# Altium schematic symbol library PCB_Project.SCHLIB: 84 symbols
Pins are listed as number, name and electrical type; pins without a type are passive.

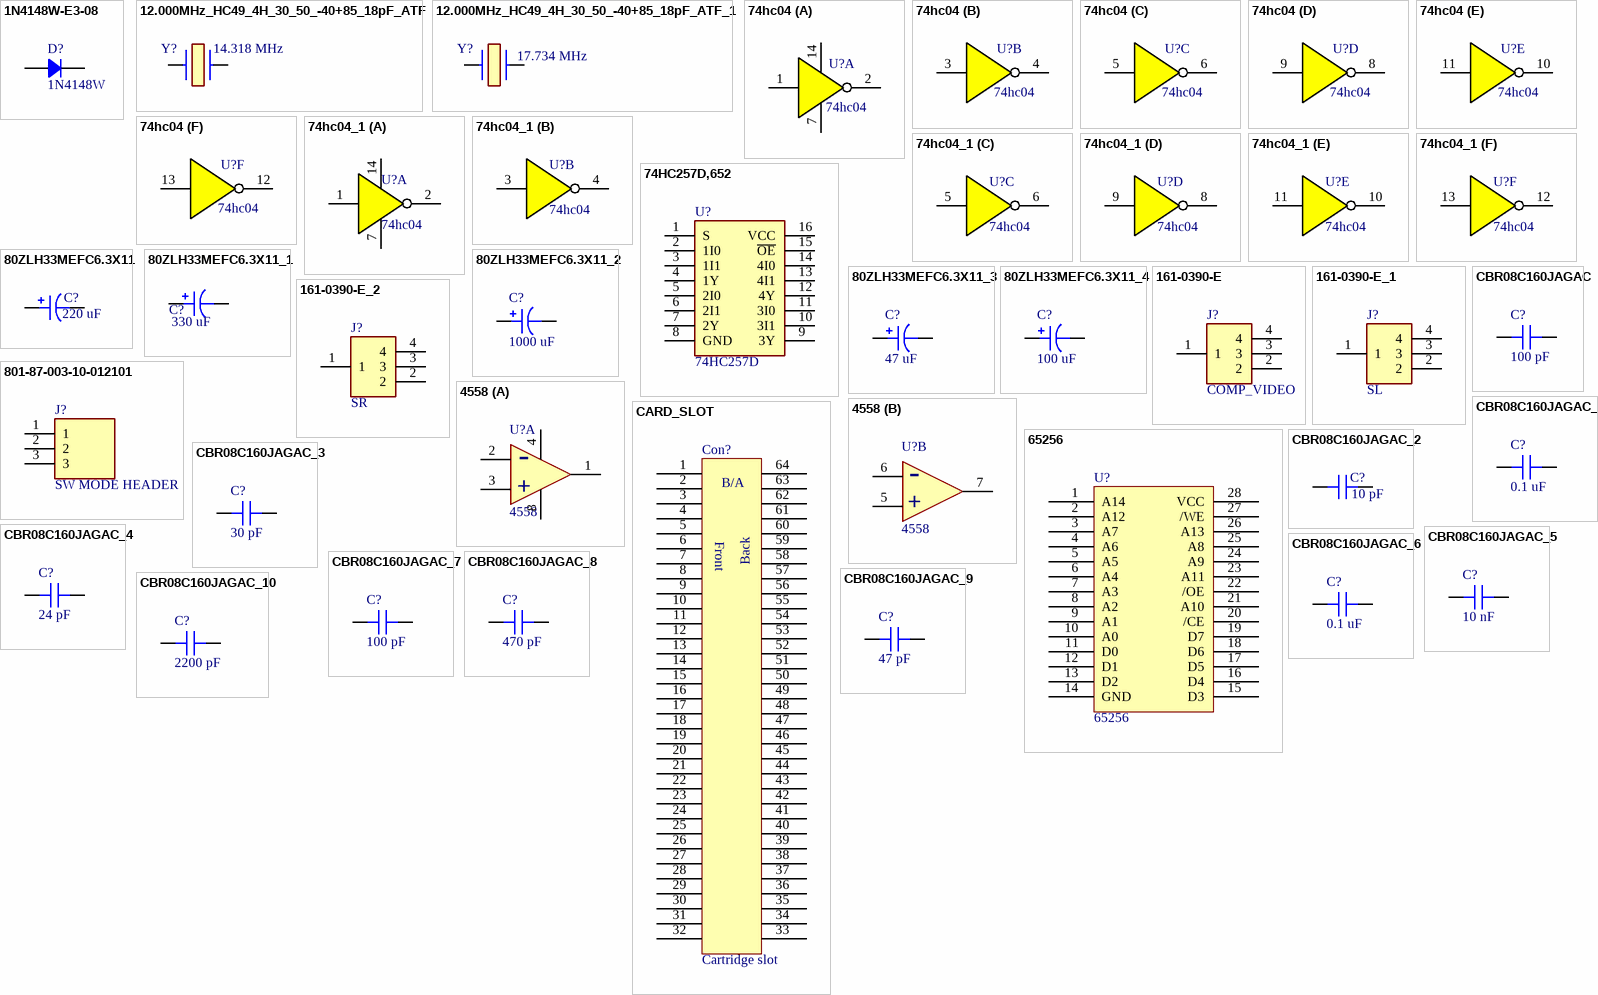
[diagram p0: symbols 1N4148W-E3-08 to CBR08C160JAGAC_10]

## 1N4148W-E3-08
designator D?, comment 1N4148W
DIODE GEN PURP 75V 150MA SOD123; Part Number: 1N4148W-E3-08; Manufacturer: Vishay Semiconductor Diodes Division; Current - Reverse Leakage @ Vr: 100µA @ 100V; Diode Type: Standard; Reverse Recovery Time (trr): 4ns; Speed: Small Signal =< 200mA (Io), Any Speed; Voltage - Forward (Vf) (Max) @ If: 1.2V @ 100mA
footprint SOD-123
pins: 1, 2

## 12.000MHz_HC49_4H_30_50_-40+85_18pF_ATF
designator Y?, comment 14.318 MHz
Crystal or Oscillator; Manufacturer_Name: EUROQUARTZ; Manufacturer_Part_Number: 12.000MHz HC49/4H/30/50/-40+85/18pF/ATF
footprint 12000MHzHC494H3050408518pFATF
pins: 1 CRYSTAL_1, 2 CRYSTAL_2

## 12.000MHz_HC49_4H_30_50_-40+85_18pF_ATF_1
designator Y?, comment 17.734 MHz
Crystal or Oscillator; Manufacturer_Name: EUROQUARTZ; Manufacturer_Part_Number: 12.000MHz HC49/4H/30/50/-40+85/18pF/ATF
footprint 12000MHzHC494H3050408518pFATF
pins: 1 CRYSTAL_1, 2 CRYSTAL_2

## 74hc04
designator U?
footprint SOIC127P600X175-14N
part A pins: 1 45, 2 46, 7 gnd, 14 vcc
part B pins: 3 45, 4 46
part C pins: 5 45, 6 46
part D pins: 8 46, 9 45
part E pins: 10 46, 11 45
part F pins: 12 46, 13 45

## 74hc04_1
designator U?, comment 74hc04
footprint SOIC127P600X175-14N
part A pins: 1 45, 2 46, 7 gnd, 14 vcc
part B pins: 3 45, 4 46
part C pins: 5 45, 6 46
part D pins: 8 46, 9 45
part E pins: 10 46, 11 45
part F pins: 12 46, 13 45

## 74HC257D,652
designator U?, comment 74HC257D
Integrated Circuit; Manufacturer_Name: Nexperia; Manufacturer_Part_Number: 74HC257D,652
footprint 74HC257D652
pins: 1 S, 2 1I0, 3 1I1, 4 1Y, 5 2I0, 6 2I1, 7 2Y, 8 GND, 9 3Y, 10 3I1, 11 3I0, 12 4Y, 13 4I1, 14 4I0, 15 ~{OE}, 16 VCC

## 80ZLH33MEFC6.3X11
designator C?, comment 220 uF
CAP ALUM 33UF 20% 80V RADIAL; Part Number: 80ZLH33MEFC6.3X11; manufacturer: Rubycon; Capacitance: 33µF; Lifetime @ Temp.: 6000 Hrs @ 105°C; Polarization: Polar; value: 33µF; Impedance: 570 mOhms; Ripple Current @ Low Frequency: 112.14mA @ 120Hz
footprint CAP TH ALUM ELEC D6.30mm S2.50mm H12.50mm
pins: 1, 2

## 80ZLH33MEFC6.3X11_1
designator C?, comment 330 uF
CAP ALUM 33UF 20% 80V RADIAL; Part Number: 80ZLH33MEFC6.3X11; manufacturer: Rubycon; Capacitance: 33µF; Lifetime @ Temp.: 6000 Hrs @ 105°C; Polarization: Polar; value: 33µF; Impedance: 570 mOhms; Ripple Current @ Low Frequency: 112.14mA @ 120Hz
footprint CAP TH ALUM ELEC D6.30mm S2.50mm H12.50mm
pins: 1, 2

## 80ZLH33MEFC6.3X11_2
designator C?, comment 1000 uF
CAP ALUM 33UF 20% 80V RADIAL; Part Number: 80ZLH33MEFC6.3X11; manufacturer: Rubycon; Capacitance: 33µF; Lifetime @ Temp.: 6000 Hrs @ 105°C; Polarization: Polar; value: 33µF; Impedance: 570 mOhms; Ripple Current @ Low Frequency: 112.14mA @ 120Hz
footprint CAP TH ALUM ELEC D6.30mm S2.50mm H12.50mm
pins: 1, 2

## 80ZLH33MEFC6.3X11_3
designator C?, comment 47 uF
CAP ALUM 33UF 20% 80V RADIAL; Part Number: 80ZLH33MEFC6.3X11; manufacturer: Rubycon; Capacitance: 33µF; Lifetime @ Temp.: 6000 Hrs @ 105°C; Polarization: Polar; value: 33µF; Impedance: 570 mOhms; Ripple Current @ Low Frequency: 112.14mA @ 120Hz
footprint CAP TH ALUM ELEC D6.30mm S2.50mm H12.50mm
pins: 1, 2

## 80ZLH33MEFC6.3X11_4
designator C?, comment 100 uF
CAP ALUM 33UF 20% 80V RADIAL; Part Number: 80ZLH33MEFC6.3X11; manufacturer: Rubycon; Capacitance: 33µF; Lifetime @ Temp.: 6000 Hrs @ 105°C; Polarization: Polar; value: 33µF; Impedance: 570 mOhms; Ripple Current @ Low Frequency: 112.14mA @ 120Hz
footprint CAP TH ALUM ELEC D6.30mm S2.50mm H12.50mm
pins: 1, 2

## 161-0390-E
designator J?, comment COMP_VIDEO
Connector; Manufacturer_Name: Kobiconn; Manufacturer_Part_Number: 161-0390-E
footprint 1610390E
pins: 1, 2, 3, 4

## 161-0390-E_1
designator J?, comment SL
Connector; Manufacturer_Name: Kobiconn; Manufacturer_Part_Number: 161-0390-E
footprint 1610390E
pins: 1, 2, 3, 4

## 161-0390-E_2
designator J?, comment SR
Connector; Manufacturer_Name: Kobiconn; Manufacturer_Part_Number: 161-0390-E
footprint 1610390E
pins: 1, 2, 3, 4

## 801-87-003-10-012101
designator J?, comment SW MODE HEADER
Connector; Manufacturer_Name: Preci-Dip; Manufacturer_Part_Number: 801-87-003-10-012101
footprint 8018700310012101
pins: 1, 2, 3

## 4558
designator U?
Operation amp; Manufacturer_Name: Texas Instruments; Manufacturer_Part_Number: OPA2134UA
footprint SOIC127P600X175-8N
part A pins: 1 13, 2 -, 3 10, 4 11, 8 12
part B pins: 5 11, 6 -, 7 14

## 65256
designator U?
footprint SOP28
pins: 1 A14, 2 A12, 3 A7, 4 A6, 5 A5, 6 A4, 7 A3, 8 A2, 9 A1, 10 A0, 11 D0, 12 D1, 13 D2, 14 GND, 15 D3, 16 D4, 17 D5, 18 D6, 19 D7, 20 /CE, 21 A10, 22 /OE, 23 A11, 24 A9, 25 A8, 26 A13, 27 /WE, 28 VCC

## CARD_SLOT
designator Con?, comment Cartridge slot
footprint CARD_SLOT
pins: 1 Ain, 2 Ain, 3 Ain, 4 Ain, 5 Ain, 6 Ain, 7 Ain, 8 Ain, 9 Ain, 10 Ain, 11 Ain, 12 Ain, 13 Ain, 14 Ain, 15 Ain, 16 Ain, 17 Ain, 18 Ain, 19 Ain, 20 Ain, 21 Ain, 22 Ain, 23 Ain, 24 Ain, 25 Ain, 26 Ain, 27 Ain, 28 Ain, 29 Ain, 30 Ain, 31 Ain, 32 Ain, 33 50, 34 51, 35 52, 36 53, 37 54, 38 55, 39 56, 40 57, 41 58, 42 59, 43 60, 44 61, 45 62, 46 63, 47 64, 48 65, 49 66, 50 67, 51 68, 52 69, 53 70, 54 71, 55 72, 56 73, 57 74, 58 75, 59 76, 60 77, 61 78, 62 79, 63 80, 64 81

## CBR08C160JAGAC
designator C?, comment 100 pF
CAP CER 16PF 250V C0G/NP0 0805; Part Number: CBR08C160JAGAC; manufacturer: KEMET; Temperature Coefficient: C0G, NP0; Tolerance: ±5%
footprint CAP 0805_2012
pins: 1, 2

## CBR08C160JAGAC_1
designator C?, comment 0.1 uF
CAP CER 16PF 250V C0G/NP0 0805; Part Number: CBR08C160JAGAC; manufacturer: KEMET; Temperature Coefficient: C0G, NP0; Tolerance: ±5%
footprint CAP 0805_2012
pins: 1, 2

## CBR08C160JAGAC_2
designator C?, comment 10 pF
CAP CER 16PF 250V C0G/NP0 0805; Part Number: CBR08C160JAGAC; manufacturer: KEMET; Temperature Coefficient: C0G, NP0; Tolerance: ±5%
footprint CAP 0805_2012
pins: 1, 2

## CBR08C160JAGAC_3
designator C?, comment 30 pF
CAP CER 16PF 250V C0G/NP0 0805; Part Number: CBR08C160JAGAC; manufacturer: KEMET; Temperature Coefficient: C0G, NP0; Tolerance: ±5%
footprint CAP 0805_2012
pins: 1, 2

## CBR08C160JAGAC_4
designator C?, comment 24 pF
CAP CER 16PF 250V C0G/NP0 0805; Part Number: CBR08C160JAGAC; manufacturer: KEMET; Temperature Coefficient: C0G, NP0; Tolerance: ±5%
footprint CAP 0805_2012
pins: 1, 2

## CBR08C160JAGAC_5
designator C?, comment 10 nF
CAP CER 16PF 250V C0G/NP0 0805; Part Number: CBR08C160JAGAC; manufacturer: KEMET; Temperature Coefficient: C0G, NP0; Tolerance: ±5%
footprint CAP 0805_2012
pins: 1, 2

## CBR08C160JAGAC_6
designator C?, comment 0.1 uF
CAP CER 16PF 250V C0G/NP0 0805; Part Number: CBR08C160JAGAC; manufacturer: KEMET; Temperature Coefficient: C0G, NP0; Tolerance: ±5%
footprint CAP 0805_2012
pins: 1, 2

## CBR08C160JAGAC_7
designator C?, comment 100 pF
CAP CER 16PF 250V C0G/NP0 0805; Part Number: CBR08C160JAGAC; manufacturer: KEMET; Temperature Coefficient: C0G, NP0; Tolerance: ±5%
footprint CAP 0805_2012
pins: 1, 2

## CBR08C160JAGAC_8
designator C?, comment 470 pF
CAP CER 16PF 250V C0G/NP0 0805; Part Number: CBR08C160JAGAC; manufacturer: KEMET; Temperature Coefficient: C0G, NP0; Tolerance: ±5%
footprint CAP 0805_2012
pins: 1, 2

## CBR08C160JAGAC_9
designator C?, comment 47 pF
CAP CER 16PF 250V C0G/NP0 0805; Part Number: CBR08C160JAGAC; manufacturer: KEMET; Temperature Coefficient: C0G, NP0; Tolerance: ±5%
footprint CAP 0805_2012
pins: 1, 2

## CBR08C160JAGAC_10
designator C?, comment 2200 pF
CAP CER 16PF 250V C0G/NP0 0805; Part Number: CBR08C160JAGAC; manufacturer: KEMET; Temperature Coefficient: C0G, NP0; Tolerance: ±5%
footprint CAP 0805_2012
pins: 1, 2

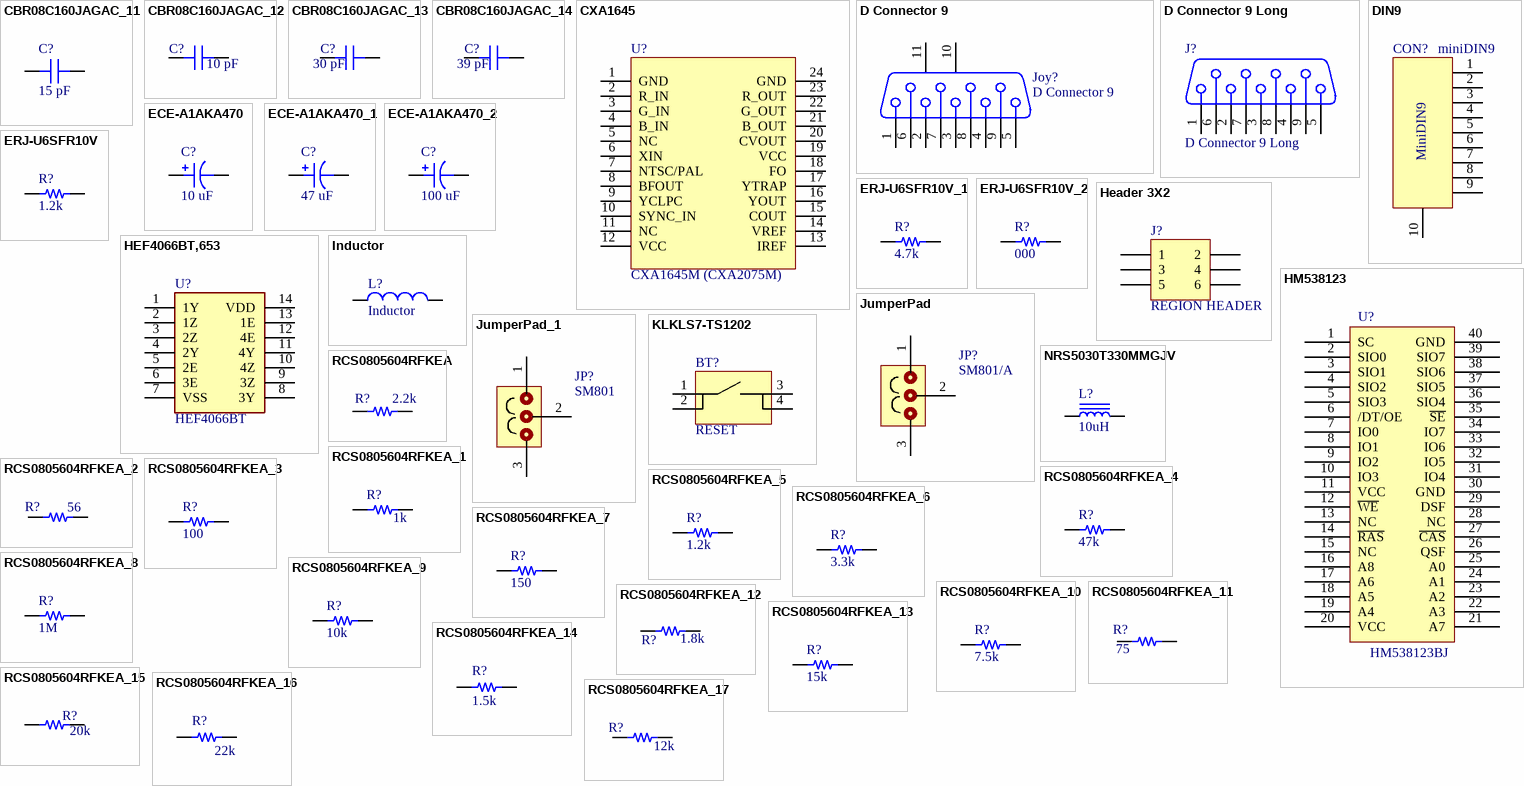
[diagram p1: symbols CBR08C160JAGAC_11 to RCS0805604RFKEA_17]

## CBR08C160JAGAC_11
designator C?, comment 15 pF
CAP CER 16PF 250V C0G/NP0 0805; Part Number: CBR08C160JAGAC; manufacturer: KEMET; Temperature Coefficient: C0G, NP0; Tolerance: ±5%
footprint CAP 0805_2012
pins: 1, 2

## CBR08C160JAGAC_12
designator C?, comment 10 pF
CAP CER 16PF 250V C0G/NP0 0805; Part Number: CBR08C160JAGAC; manufacturer: KEMET; Temperature Coefficient: C0G, NP0; Tolerance: ±5%
footprint CAP 0805_2012
pins: 1, 2

## CBR08C160JAGAC_13
designator C?, comment 30 pF
CAP CER 16PF 250V C0G/NP0 0805; Part Number: CBR08C160JAGAC; manufacturer: KEMET; Temperature Coefficient: C0G, NP0; Tolerance: ±5%
footprint CAP 0805_2012
pins: 1, 2

## CBR08C160JAGAC_14
designator C?, comment 39 pF
CAP CER 16PF 250V C0G/NP0 0805; Part Number: CBR08C160JAGAC; manufacturer: KEMET; Temperature Coefficient: C0G, NP0; Tolerance: ±5%
footprint CAP 0805_2012
pins: 1, 2

## CXA1645
designator U?, comment CXA1645M (CXA2075M)
Video coder
footprint SOP24N (SOP, 24-Leads, Body 15,90x5,65mm, Pitch 1,27mm, IPC Medium Density)
pins: 1 GND, 2 R_IN, 3 G_IN, 4 B_IN, 5 NC, 6 XIN, 7 NTSC/PAL, 8 BFOUT, 9 YCLPC, 10 SYNC_IN, 11 NC, 12 VCC, 13 IREF, 14 VREF, 15 COUT, 16 YOUT, 17 YTRAP, 18 FO, 19 VCC, 20 CVOUT, 21 B_OUT, 22 G_OUT, 23 R_OUT, 24 GND

## D Connector 9
designator Joy?
Receptacle Assembly, 9 Position, Right Angle; PackageDocument: O; Positions: 9
footprint DSUB1.385-2H9 (Connector; D Subminiature; 9 Position; Right Angle; Pitch 1.385 mm)
signal-integrity model Connector
pins: 1, 2, 3, 4, 5, 6, 7, 8, 9, 10 MH1, 11 MH2

## D Connector 9 Long
designator J?
Receptacle Assembly, 9 Position, Right Angle; PackageDocument: O; Positions: 9
footprint DSUB1.385-2H9_LONG (Connector; D Subminiature; 9 Position; Right Angle; Pitch 1.385 mm)
pins: 1, 2, 3, 4, 5, 6, 7, 8, 9

## DIN9
designator CON?, comment miniDIN9
footprint miniDIN9
pins: 1 7, 2 8, 3 9, 4 10, 5 11, 6 12, 7 13, 8 14, 9 15, 10 16

## ECE-A1AKA470
designator C?, comment 10 uF
CAP ALUM 47UF 20% 10V RADIAL; Part Number: ECE-A1AKA470; manufacturer: Panasonic Electronic Components; Capacitance: 47µF; Lifetime @ Temp.: 1000 Hrs @ 85°C; Polarization: Polar; Ripple Current @ High Frequency: 110.5mA @ 10kHz; value: 47µF
footprint CAP TH ALUM ELEC D5.00mm S2.00mm H7.00mm
pins: 1, 2

## ECE-A1AKA470_1
designator C?, comment 47 uF
CAP ALUM 47UF 20% 10V RADIAL; Part Number: ECE-A1AKA470; manufacturer: Panasonic Electronic Components; Capacitance: 47µF; Lifetime @ Temp.: 1000 Hrs @ 85°C; Polarization: Polar; Ripple Current @ High Frequency: 110.5mA @ 10kHz; value: 47µF
footprint CAP TH ALUM ELEC D5.00mm S2.00mm H7.00mm
pins: 1, 2

## ECE-A1AKA470_2
designator C?, comment 100 uF
CAP ALUM 47UF 20% 10V RADIAL; Part Number: ECE-A1AKA470; manufacturer: Panasonic Electronic Components; Capacitance: 47µF; Lifetime @ Temp.: 1000 Hrs @ 85°C; Polarization: Polar; Ripple Current @ High Frequency: 110.5mA @ 10kHz; value: 47µF
footprint CAP TH ALUM ELEC D5.00mm S2.00mm H7.00mm
pins: 1, 2

## ERJ-U6SFR10V
designator R?, comment 1.2k
RES 0.1 OHM 1% 1/4W 0805; Part Number: ERJ-U6SFR10V; Manufacturer: Panasonic Electronic Components; Power (Watts): 0.25W, 1/4W; Resistance: 100 mOhms; Temperature Coefficient: ±150ppm/°C
footprint RES 0805_2012
pins: 1, 2

## ERJ-U6SFR10V_1
designator R?, comment 4.7k
RES 0.1 OHM 1% 1/4W 0805; Part Number: ERJ-U6SFR10V; Manufacturer: Panasonic Electronic Components; Power (Watts): 0.25W, 1/4W; Resistance: 100 mOhms; Temperature Coefficient: ±150ppm/°C
footprint RES 0805_2012
pins: 1, 2

## ERJ-U6SFR10V_2
designator R?, comment 000
RES 0.1 OHM 1% 1/4W 0805; Part Number: ERJ-U6SFR10V; Manufacturer: Panasonic Electronic Components; Power (Watts): 0.25W, 1/4W; Resistance: 100 mOhms; Temperature Coefficient: ±150ppm/°C
footprint RES 0805_2012
pins: 1, 2

## Header 3X2
designator J?, comment REGION HEADER
Header, 3-Pin, Dual row
footprint HDR2X3 (Connector; Header; 3x2 Position)
signal-integrity model Connector
pins: 1, 2, 3, 4, 5, 6

## HEF4066BT,653
designator U?, comment HEF4066BT
Integrated Circuit; Manufacturer_Name: Nexperia; Manufacturer_Part_Number: HEF4066BT,653
footprint SOIC127P600X175-14N
pins: 1 1Y, 2 1Z, 3 2Z, 4 2Y, 5 2E, 6 3E, 7 VSS, 8 3Y, 9 3Z, 10 4Z, 11 4Y, 12 4E, 13 1E, 14 VDD

## HM538123
designator U?, comment HM538123BJ
footprint SOP40
pins: 1 SC, 2 SIO0, 3 SIO1, 4 SIO2, 5 SIO3, 6 /DT/OE, 7 IO0, 8 IO1, 9 IO2, 10 IO3, 11 VCC, 12 ~{W}~{E}, 13 NC, 14 ~{R}~{A}~{S}, 15 NC, 16 A8, 17 A6, 18 A5, 19 A4, 20 VCC, 21 A7, 22 A3, 23 A2, 24 A1, 25 A0, 26 QSF, 27 ~{C}~{A}~{S}, 28 NC, 29 DSF, 30 GND, 31 IO4, 32 IO5, 33 IO6, 34 IO7, 35 ~{S}~{E}, 36 SIO4, 37 SIO5, 38 SIO6, 39 SIO7, 40 GND

## Inductor
designator L?
footprint Inductor vertical
pins: 1, 2

## JumperPad
designator JP?, comment SM801/A
footprint JumperPad
pins: 1 15, 2 16, 3 17

## JumperPad_1
designator JP?, comment SM801
footprint JumperPad
pins: 1 15, 2 16, 3 17

## KLKLS7-TS1202
designator BT?, comment RESET
KLS7-TS1202
footprint KLS7-12
pins: 1 8, 2 10, 3 9, 4 11

## NRS5030T330MMGJV
designator L?, comment 10uH
FIXED IND 33UH 800MA 292.5 MOHM; Part Number: NRS5030T330MMGJV; Manufacturer: Taiyo Yuden; Current - Saturation: 1.15A; DC Resistance (DCR): 292.5mOhm Max; Frequency - Self Resonant: 10MHz; Inductance: 33 µH; Inductance Frequency - Test: 100 kHz; Material - Core: Ferrite; Shielding: Shielded; Tolerance: ±20%; Type: Drum Core, Wirewound; Value: 33 µH
footprint TAIYO YUDEN NRS5030
pins: 1, 2

## RCS0805604RFKEA
designator R?, comment 2.2k
RES SMD 604 OHM 1% 1/2W 0805; Part Number: RCS0805604RFKEA; Manufacturer: Vishay Dale; Power (Watts): 0.5W, 1/2W; Resistance: 604 Ohms; Temperature Coefficient: ±100ppm/°C
footprint RES 0805_2012
pins: 1, 2

## RCS0805604RFKEA_1
designator R?, comment 1k
RES SMD 604 OHM 1% 1/2W 0805; Part Number: RCS0805604RFKEA; Manufacturer: Vishay Dale; Power (Watts): 0.5W, 1/2W; Resistance: 604 Ohms; Temperature Coefficient: ±100ppm/°C
footprint RES 0805_2012
pins: 1, 2

## RCS0805604RFKEA_2
designator R?, comment 56
RES SMD 604 OHM 1% 1/2W 0805; Part Number: RCS0805604RFKEA; Manufacturer: Vishay Dale; Power (Watts): 0.5W, 1/2W; Resistance: 604 Ohms; Temperature Coefficient: ±100ppm/°C
footprint RES 0805_2012
pins: 1, 2

## RCS0805604RFKEA_3
designator R?, comment 100
RES SMD 604 OHM 1% 1/2W 0805; Part Number: RCS0805604RFKEA; Manufacturer: Vishay Dale; Power (Watts): 0.5W, 1/2W; Resistance: 604 Ohms; Temperature Coefficient: ±100ppm/°C
footprint RES 0805_2012
pins: 1, 2

## RCS0805604RFKEA_4
designator R?, comment 47k
RES SMD 604 OHM 1% 1/2W 0805; Part Number: RCS0805604RFKEA; Manufacturer: Vishay Dale; Power (Watts): 0.5W, 1/2W; Resistance: 604 Ohms; Temperature Coefficient: ±100ppm/°C
footprint RES 0805_2012
pins: 1, 2

## RCS0805604RFKEA_5
designator R?, comment 1.2k
RES SMD 604 OHM 1% 1/2W 0805; Part Number: RCS0805604RFKEA; Manufacturer: Vishay Dale; Power (Watts): 0.5W, 1/2W; Resistance: 604 Ohms; Temperature Coefficient: ±100ppm/°C
footprint RES 0805_2012
pins: 1, 2

## RCS0805604RFKEA_6
designator R?, comment 3.3k
RES SMD 604 OHM 1% 1/2W 0805; Part Number: RCS0805604RFKEA; Manufacturer: Vishay Dale; Power (Watts): 0.5W, 1/2W; Resistance: 604 Ohms; Temperature Coefficient: ±100ppm/°C
footprint RES 0805_2012
pins: 1, 2

## RCS0805604RFKEA_7
designator R?, comment 150
RES SMD 604 OHM 1% 1/2W 0805; Part Number: RCS0805604RFKEA; Manufacturer: Vishay Dale; Power (Watts): 0.5W, 1/2W; Resistance: 604 Ohms; Temperature Coefficient: ±100ppm/°C
footprint RES 0805_2012
pins: 1, 2

## RCS0805604RFKEA_8
designator R?, comment 1M
RES SMD 604 OHM 1% 1/2W 0805; Part Number: RCS0805604RFKEA; Manufacturer: Vishay Dale; Power (Watts): 0.5W, 1/2W; Resistance: 604 Ohms; Temperature Coefficient: ±100ppm/°C
footprint RES 0805_2012
pins: 1, 2

## RCS0805604RFKEA_9
designator R?, comment 10k
RES SMD 604 OHM 1% 1/2W 0805; Part Number: RCS0805604RFKEA; Manufacturer: Vishay Dale; Power (Watts): 0.5W, 1/2W; Resistance: 604 Ohms; Temperature Coefficient: ±100ppm/°C
footprint RES 0805_2012
pins: 1, 2

## RCS0805604RFKEA_10
designator R?, comment 7.5k
RES SMD 604 OHM 1% 1/2W 0805; Part Number: RCS0805604RFKEA; Manufacturer: Vishay Dale; Power (Watts): 0.5W, 1/2W; Resistance: 604 Ohms; Temperature Coefficient: ±100ppm/°C
footprint RES 0805_2012
pins: 1, 2

## RCS0805604RFKEA_11
designator R?, comment 75
RES SMD 604 OHM 1% 1/2W 0805; Part Number: RCS0805604RFKEA; Manufacturer: Vishay Dale; Power (Watts): 0.5W, 1/2W; Resistance: 604 Ohms; Temperature Coefficient: ±100ppm/°C
footprint RES 0805_2012
pins: 1, 2

## RCS0805604RFKEA_12
designator R?, comment 1.8k
RES SMD 604 OHM 1% 1/2W 0805; Part Number: RCS0805604RFKEA; Manufacturer: Vishay Dale; Power (Watts): 0.5W, 1/2W; Resistance: 604 Ohms; Temperature Coefficient: ±100ppm/°C
footprint RES 0805_2012
pins: 1, 2

## RCS0805604RFKEA_13
designator R?, comment 15k
RES SMD 604 OHM 1% 1/2W 0805; Part Number: RCS0805604RFKEA; Manufacturer: Vishay Dale; Power (Watts): 0.5W, 1/2W; Resistance: 604 Ohms; Temperature Coefficient: ±100ppm/°C
footprint RES 0805_2012
pins: 1, 2

## RCS0805604RFKEA_14
designator R?, comment 1.5k
RES SMD 604 OHM 1% 1/2W 0805; Part Number: RCS0805604RFKEA; Manufacturer: Vishay Dale; Power (Watts): 0.5W, 1/2W; Resistance: 604 Ohms; Temperature Coefficient: ±100ppm/°C
footprint RES 0805_2012
pins: 1, 2

## RCS0805604RFKEA_15
designator R?, comment 20k
RES SMD 604 OHM 1% 1/2W 0805; Part Number: RCS0805604RFKEA; Manufacturer: Vishay Dale; Power (Watts): 0.5W, 1/2W; Resistance: 604 Ohms; Temperature Coefficient: ±100ppm/°C
footprint RES 0805_2012
pins: 1, 2

## RCS0805604RFKEA_16
designator R?, comment 22k
RES SMD 604 OHM 1% 1/2W 0805; Part Number: RCS0805604RFKEA; Manufacturer: Vishay Dale; Power (Watts): 0.5W, 1/2W; Resistance: 604 Ohms; Temperature Coefficient: ±100ppm/°C
footprint RES 0805_2012
pins: 1, 2

## RCS0805604RFKEA_17
designator R?, comment value 12k  (hidden comment: 22k)
RES SMD 604 OHM 1% 1/2W 0805; Part Number: RCS0805604RFKEA; Manufacturer: Vishay Dale; Power (Watts): 0.5W, 1/2W; Resistance: 604 Ohms; Temperature Coefficient: ±100ppm/°C
footprint RES 0805_2012
pins: 1, 2

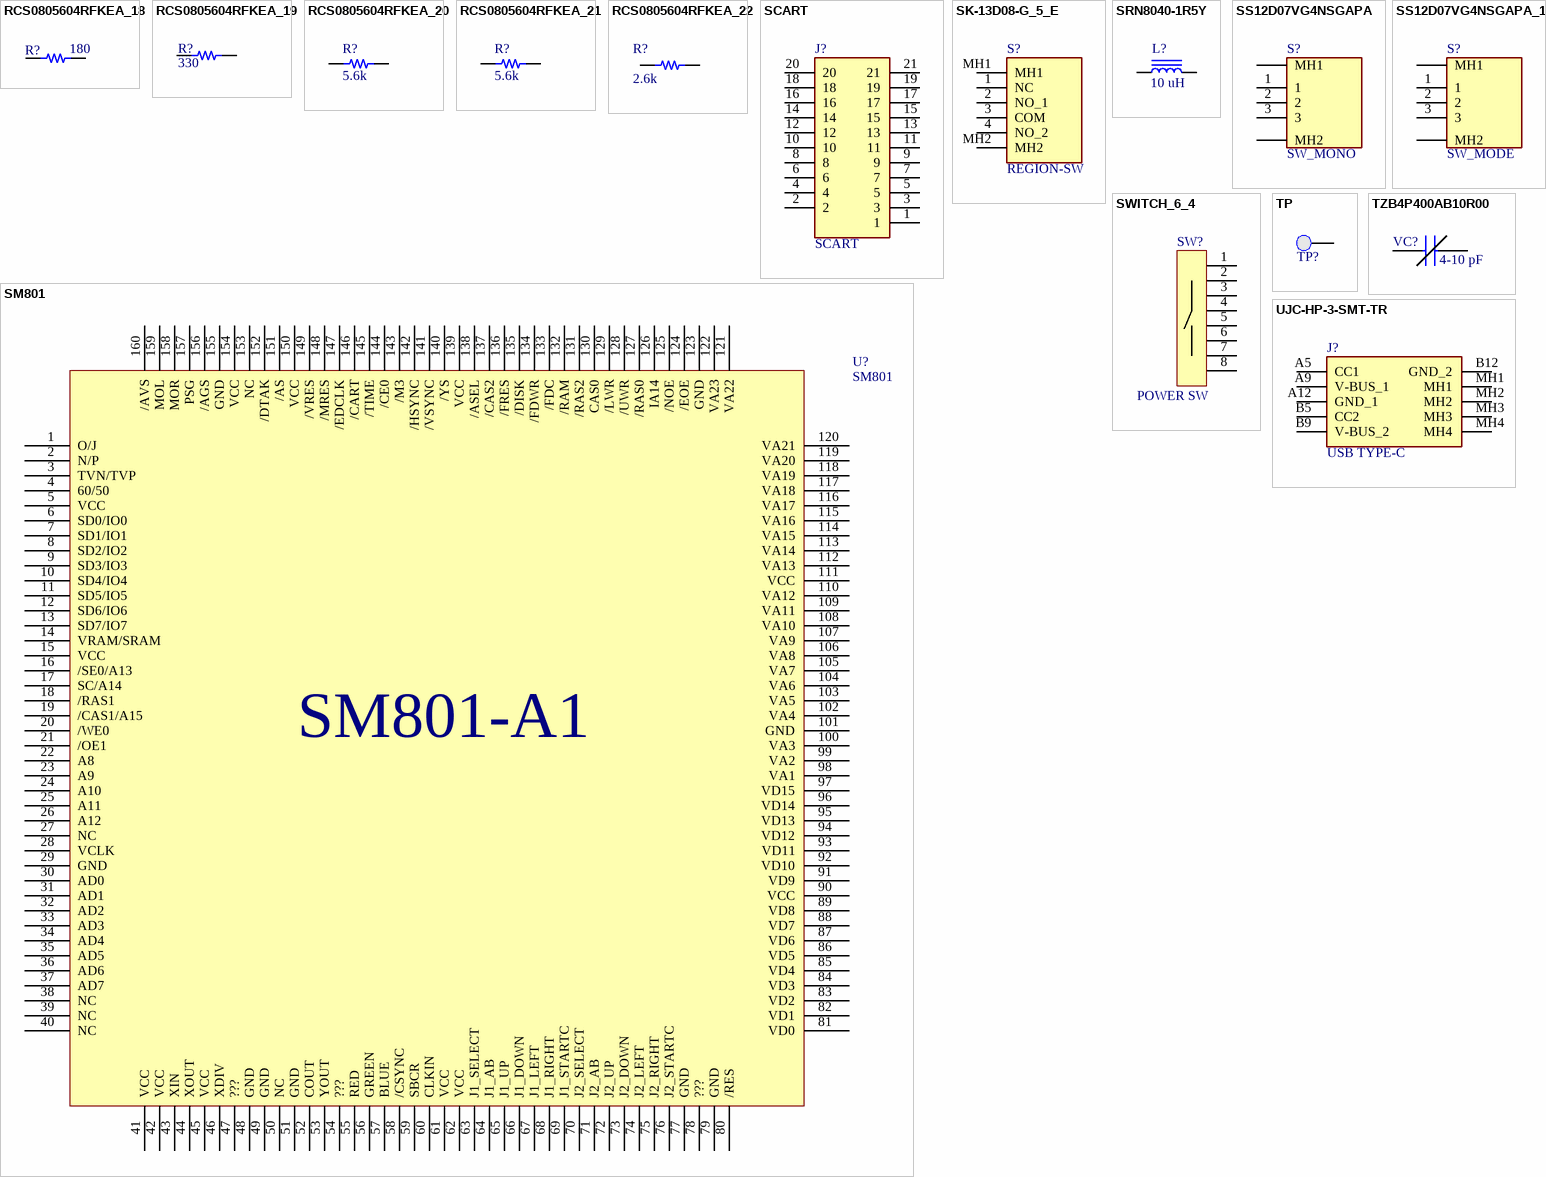
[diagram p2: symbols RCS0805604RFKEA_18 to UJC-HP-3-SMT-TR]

## RCS0805604RFKEA_18
designator R?, comment 180
RES SMD 604 OHM 1% 1/2W 0805; Part Number: RCS0805604RFKEA; Manufacturer: Vishay Dale; Power (Watts): 0.5W, 1/2W; Resistance: 604 Ohms; Temperature Coefficient: ±100ppm/°C
footprint RES 0805_2012
pins: 1, 2

## RCS0805604RFKEA_19
designator R?, comment 330
RES SMD 604 OHM 1% 1/2W 0805; Part Number: RCS0805604RFKEA; Manufacturer: Vishay Dale; Power (Watts): 0.5W, 1/2W; Resistance: 604 Ohms; Temperature Coefficient: ±100ppm/°C
footprint RES 0805_2012
pins: 1, 2

## RCS0805604RFKEA_20
designator R?, comment 5.6k
RES SMD 604 OHM 1% 1/2W 0805; Part Number: RCS0805604RFKEA; Manufacturer: Vishay Dale; Power (Watts): 0.5W, 1/2W; Resistance: 604 Ohms; Temperature Coefficient: ±100ppm/°C
footprint RES 0805_2012
pins: 1, 2

## RCS0805604RFKEA_21
designator R?, comment 5.6k
RES SMD 604 OHM 1% 1/2W 0805; Part Number: RCS0805604RFKEA; Manufacturer: Vishay Dale; Power (Watts): 0.5W, 1/2W; Resistance: 604 Ohms; Temperature Coefficient: ±100ppm/°C
footprint RES 0805_2012
pins: 1, 2

## RCS0805604RFKEA_22
designator R?, comment 2.6k
RES SMD 604 OHM 1% 1/2W 0805; Part Number: RCS0805604RFKEA; Manufacturer: Vishay Dale; Power (Watts): 0.5W, 1/2W; Resistance: 604 Ohms; Temperature Coefficient: ±100ppm/°C
footprint RES 0805_2012
pins: 1, 2

## SCART
designator J?
Connector; Manufacturer_Name: PRO SIGNAL; Manufacturer_Part_Number: PSG01601
footprint PSG01601
pins: 1, 2, 3, 4, 5, 6, 7, 8, 9, 10, 11, 12, 13, 14, 15, 16, 17, 18, 19, 20, 21

## SK-13D08-G_5_E
designator S?, comment REGION-SW
Switch; Manufacturer_Name: C & K COMPONENTS; Manufacturer_Part_Number: SK-13D08-G 5 E
footprint SK13D08G5E
pins: 1 NC, 2 NO_1, 3 COM, 4 NO_2, MH1, MH2

## SM801
designator U?
footprint SM801-A1
pins: 1 O/J, 2 N/P, 3 TVN/TVP, 4 60/50, 5 VCC, 6 SD0/IO0, 7 SD1/IO1, 8 SD2/IO2, 9 SD3/IO3, 10 SD4/IO4, 11 SD5/IO5, 12 SD6/IO6, 13 SD7/IO7, 14 VRAM/SRAM, 15 VCC, 16 /SE0/A13, 17 SC/A14, 18 /RAS1, 19 /CAS1/A15, 20 /WE0, 21 /OE1, 22 A8, 23 A9, 24 A10, 25 A11, 26 A12, 27 NC, 28 VCLK, 29 GND, 30 AD0, 31 AD1, 32 AD2, 33 AD3, 34 AD4, 35 AD5, 36 AD6, 37 AD7, 38 NC, 39 NC, 40 NC, 41 VCC, 42 VCC, 43 XIN, 44 XOUT, 45 VCC, 46 XDIV, 47 ???, 48 GND, 49 GND, 50 NC, 51 GND, 52 COUT, 53 YOUT, 54 ???, 55 RED, 56 GREEN, 57 BLUE, 58 /CSYNC, 59 SBCR, 60 CLKIN, 61 VCC, 62 VCC, 63 J1_SELECT, 64 J1_AB, 65 J1_UP, 66 J1_DOWN, 67 J1_LEFT, 68 J1_RIGHT, 69 J1_STARTC, 70 J2_SELECT, 71 J2_AB, 72 J2_UP, 73 J2_DOWN, 74 J2_LEFT, 75 J2_RIGHT, 76 J2_STARTC, 77 GND, 78 ???, 79 GND, 80 /RES, 81 VD0, 82 VD1, 83 VD2, 84 VD3, 85 VD4, 86 VD5, 87 VD6, 88 VD7, 89 VD8, 90 VCC, 91 VD9, 92 VD10, 93 VD11, 94 VD12, 95 VD13, 96 VD14, 97 VD15, 98 VA1, 99 VA2, 100 VA3, 101 GND, 102 VA4, 103 VA5, 104 VA6, 105 VA7, 106 VA8, 107 VA9, 108 VA10, 109 VA11, 110 VA12, 111 VCC, 112 VA13, 113 VA14, 114 VA15, 115 VA16, 116 VA17, 117 VA18, 118 VA19, 119 VA20, 120 VA21, 121 VA22, 122 VA23, 123 GND, 124 /EOE, 125 /NOE, 126 IA14, 127 /RAS0, 128 /UWR, 129 /LWR, 130 CAS0, 131 /RAS2, 132 /RAM, 133 /FDC, 134 /FDWR, 135 /DISK, 136 /FRES, 137 /CAS2, 138 /ASEL, 139 VCC, 140 /YS, 141 /VSYNC, 142 /HSYNC, 143 /M3, 144 /CE0, 145 /TIME, 146 /CART, 147 /EDCLK, 148 /MRES, 149 /VRES, 150 VCC, 151 /AS, 152 /DTAK, 153 NC, 154 VCC, 155 GND, 156 /AGS, 157 PSG, 158 MOR, 159 MOL, 160 /AVS

## SRN8040-1R5Y
designator L?, comment 10 uH
FIXED IND 1.5UH 7A 11 MOHM SMD; Part Number: SRN8040-1R5Y; Manufacturer: Bourns Inc.; Current - Saturation: 8.2A; DC Resistance (DCR): 11mOhm Max; Frequency - Self Resonant: 55MHz; Inductance: 1.5 µH; Inductance Frequency - Test: 100 kHz; Material - Core: Ferrite; Q @ Freq: 13 @ 7.96MHz; Shielding: Semi-Shielded; Tolerance: ±30%; Type: Drum Core, Wirewound; Value: 1.5 µH
footprint BOURNS SRN8040
pins: 1, 2

## SS12D07VG4NSGAPA
designator S?, comment SW_MONO
Switch; Manufacturer_Name: C & K COMPONENTS; Manufacturer_Part_Number: SS12D07VG4NSGAPA
footprint SS12D07VG4NSGAPA
pins: 1, 2, 3, MH1, MH2

## SS12D07VG4NSGAPA_1
designator S?, comment SW_MODE
Switch; Manufacturer_Name: C & K COMPONENTS; Manufacturer_Part_Number: SS12D07VG4NSGAPA
footprint SS12D07VG4NSGAPA
pins: 1, 2, 3, MH1, MH2

## SWITCH_6_4
designator SW?, comment POWER SW
footprint SW_6_4
pins: 1 6, 2 7, 3 8, 4 9, 5 10, 6 11, 7 12, 8 13

## TP
designator TP?, comment Test point  (value not drawn)
footprint TP (Test point)
pins: 1 "Test point"

## TZB4P400AB10R00
designator VC?, comment 4-10 pF
Capacitor; Manufacturer_Name: Murata Electronics; Manufacturer_Part_Number: TZB4P400AB10R00
footprint CAPPM5040X320N
pins: 1 +, 2 -

## UJC-HP-3-SMT-TR
designator J?, comment USB TYPE-C
Connector; Manufacturer_Name: CUI Inc.; Manufacturer_Part_Number: UJC-HP-3-SMT-TR
footprint UJCHP3SMTTR
pins: A5 CC1, A9 V-BUS_1, A12 GND_1, B5 CC2, B9 V-BUS_2, B12 GND_2, MH1, MH2, MH3, MH4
